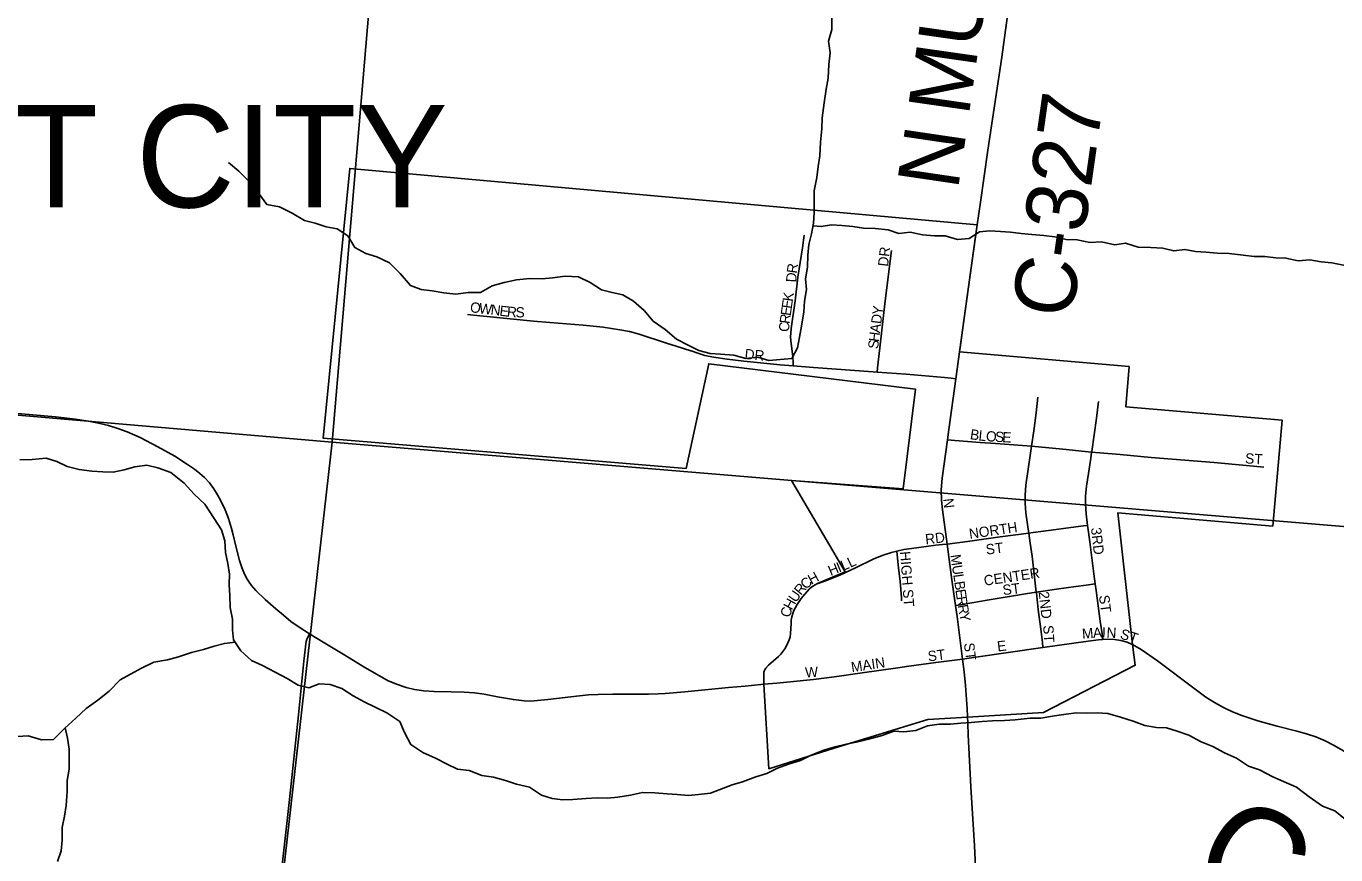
# Model space of a CAD drawing. Extents: x 1410790 to 1770854, y 566777 to 831614.
# Drawn here: x 1589830 to 1596228, y 734476 to 738525 of the extents above; entities that cross this region are included whole.
import ezdxf

# ---------------------------------------------------------------- set-up
doc = ezdxf.new("R2010")
doc.units = 0
for name, color, linetype in [('GM_X_City_Street', 7, 'Continuous'), ('GM_X_City_Street_Text', 7, 'Continuous'), ('GM_X_Corporation', 7, 'Continuous'), ('GM_X_Corporation_Text', 7, 'Continuous'), ('GM_X_County_Road', 7, 'Continuous'), ('GM_X_County_Road_Text', 7, 'Continuous'), ('GM_X_Minor_River', 7, 'Continuous'), ('GM_X_Minor_River_Text', 7, 'Continuous'), ('GM_X_Section', 7, 'Continuous'), ('GM_X_Township_Road', 7, 'Continuous')]:
    doc.layers.add(name, color=color, linetype=linetype)

msp = doc.modelspace()

# ---------------------------------------------------------------- linework, layer by layer
at = {"layer": 'GM_X_City_Street'}
for points in [[(1593577.7, 736865.5), (1593576.8, 736880.9), (1593575, 736911.3), (1593566.4, 736974.7), (1593564.6, 737005.9), (1593567.2, 737047.6), (1593586.3, 737183), (1593600.2, 737298.5), (1593621.9, 737441.7), (1593630.6, 737504.2)], [(1593986.7, 736834.9), (1593989.1, 736855.8), (1594000.5, 736953.2), (1594027.1, 737182.2), (1594056.8, 737428.7)], [(1591985, 737116.1), (1592045.5, 737109.3), (1592098.5, 737104.9), (1592146, 737100), (1592210.6, 737092.9), (1592307.6, 737083.2), (1592388.7, 737076.9), (1592551.3, 737063.4), (1592648.7, 737053.5), (1592729.4, 737041.9), (1592777.4, 737032.4), (1592824.7, 737019.9), (1592958.5, 736976.8), (1593004.7, 736961.7), (1593077.7, 736938.3), (1593078.2, 736938.1)], [(1593078.2, 736938.1), (1593110.6, 736927), (1593145.4, 736916.5), (1593187, 736907.9), (1593255, 736897.6), (1593335.7, 736888.1), (1593513.7, 736870.5), (1593577.7, 736865.5)], [(1594372.2, 736802), (1594373.8, 736813.6), (1594390.2, 736933.9), (1594392.9, 736953.8)], [(1593577.7, 736865.5), (1593675.8, 736857.7), (1593967.7, 736836.4), (1593986.7, 736834.9)], [(1593986.7, 736834.9), (1594129.8, 736823.9), (1594203.3, 736817.6)], [(1594203.3, 736817.6), (1594203.5, 736817.6), (1594315.8, 736807.6), (1594349.4, 736804.3), (1594372.2, 736802)], [(1594330.9, 736504.3), (1594337.6, 736553.7), (1594372.2, 736802)], [(1594741.8, 736472.2), (1594752.2, 736547.8), (1594763.4, 736635.3), (1594773, 736712.6)], [(1595035.2, 736443.9), (1595035.7, 736446.8), (1595058.5, 736610.1), (1595069.1, 736690.5)], [(1594329, 735994.4), (1594307.1, 736161.4), (1594302, 736209.5), (1594300.5, 736259.8), (1594305.6, 736316.6), (1594330.9, 736504.3)], [(1594330.9, 736504.3), (1594367.5, 736501.3), (1594429.2, 736496.4), (1594490.8, 736491.2), (1594565.3, 736486.1), (1594741.8, 736472.2)], [(1594727.7, 736047.6), (1594723.4, 736078.7), (1594713.9, 736147.5), (1594709.6, 736192.6), (1594709.6, 736233.4), (1594713.9, 736282), (1594735.6, 736427.9), (1594741.8, 736472.2)], [(1594741.8, 736472.2), (1594894.8, 736457.5), (1595035.2, 736443.9)], [(1595015.6, 736085.9), (1595009.1, 736141.6), (1595004.8, 736190.6), (1595004.9, 736207), (1595005.6, 736229.1), (1595010.8, 736276.8), (1595019.5, 736338.5), (1595030.8, 736414.8), (1595035.2, 736443.9)], [(1595035.2, 736443.9), (1595075.7, 736440), (1595174.3, 736431.5)], [(1595174.3, 736431.5), (1595325.6, 736417.9), (1595633.1, 736392.2), (1595859.6, 736372.2), (1595875.8, 736371)], [(1594727.7, 736047.6), (1594749.5, 736050.5), (1594861.7, 736065.3), (1594909.5, 736072.3), (1594995.2, 736083.2), (1595015.6, 736085.9)], [(1595052.4, 735800), (1595045.8, 735848.7), (1595026.4, 736005.1), (1595016.9, 736075.4), (1595015.6, 736085.9)], [(1594329, 735994.4), (1594428.7, 736007.6), (1594589, 736029.1), (1594727.7, 736047.6)], [(1594764.7, 735758.7), (1594743.8, 735934.9), (1594734.2, 735998.9), (1594727.7, 736047.6)], [(1593698.9, 735802.4), (1593747.1, 735819), (1593805.4, 735842.1), (1593882.1, 735877.7), (1593968.4, 735920.2), (1594012.5, 735939), (1594058.1, 735954.1), (1594083.3, 735960)], [(1594083.3, 735960), (1594117.3, 735967.7), (1594180, 735976.9), (1594274.6, 735988.4), (1594306.2, 735991.9), (1594329, 735994.4)], [(1594107, 735716.4), (1594106.1, 735732.6), (1594100, 735813.7), (1594091.7, 735877.3), (1594083.3, 735960)], [(1594369.7, 735694.6), (1594351.9, 735819.8), (1594329, 735994.4)], [(1593434, 735309.5), (1593433.3, 735332.5), (1593432.8, 735359.8), (1593433.8, 735368.1), (1593435.1, 735373), (1593436.6, 735376.8), (1593440.6, 735383.5), (1593444.1, 735388.4), (1593457.1, 735403.2), (1593505.1, 735444.6), (1593516.3, 735456.5), (1593526.6, 735469.1), (1593535.9, 735482.6), (1593544.8, 735497.8), (1593551.4, 735511.2), (1593557.4, 735526.4), (1593561.8, 735542), (1593564.3, 735558.1), (1593566.4, 735607), (1593567.9, 735623.3), (1593570.6, 735639.4), (1593574.7, 735655.2), (1593580.4, 735670.6), (1593587.5, 735685.2), (1593596, 735699.2), (1593616.8, 735728.7), (1593633.3, 735749.5), (1593645.5, 735762.6), (1593655, 735773.9), (1593668.9, 735786), (1593683.7, 735795.5), (1593696.1, 735801.4), (1593698.9, 735802.4)], [(1594369.7, 735694.6), (1594396.4, 735698.3), (1594412.6, 735700.5), (1594525.2, 735720.4), (1594712.2, 735750.8), (1594764.7, 735758.7)], [(1594764.7, 735758.7), (1594798.4, 735764.9), (1594862.8, 735773.7), (1594958.7, 735787.2), (1595008.2, 735794.2), (1595052.4, 735800)], [(1594797, 735488.5), (1594794.3, 735513), (1594787.1, 735578), (1594774.1, 735675.5), (1594765, 735756.6), (1594764.7, 735758.7)], [(1595089.1, 735528.5), (1595085.8, 735555.9), (1595076.8, 735617.1), (1595056.9, 735767.4), (1595052.4, 735800)], [(1594404.8, 735432.9), (1594377.4, 735641.2), (1594369.7, 735694.6)], [(1594797, 735488.5), (1595017.9, 735520.2), (1595082.2, 735528.2), (1595089.1, 735528.5)], [(1595089.1, 735528.5), (1595114.3, 735529.6), (1595146.2, 735527.9), (1595177.8, 735522.8), (1595208.7, 735514.4), (1595233.4, 735504.5)], [(1594404.8, 735432.9), (1594469.7, 735441.5), (1594797, 735488.5)], [(1593434, 735309.5), (1593497.9, 735315.4), (1593676.2, 735333.6), (1593789.5, 735347.3), (1593902.3, 735364.3), (1594099, 735391.7), (1594131.1, 735395.6), (1594274.7, 735415.9), (1594404.8, 735432.9)], [(1594429.9, 735117.3), (1594428.4, 735153.1), (1594426.6, 735188.8), (1594418.5, 735302.8), (1594411.9, 735369.5), (1594404.8, 735432.9)]]:
    msp.add_lwpolyline(points, dxfattribs=at)
at = {"layer": 'GM_X_Corporation'}
msp.add_lwpolyline([(1593596, 735699.2), (1593616.8, 735728.7), (1593633.3, 735749.5), (1593645.5, 735762.6), (1593655, 735773.8), (1593668.9, 735786), (1593683.7, 735795.5), (1593696.1, 735801.4), (1593830.5, 735858.3), (1593568.6, 736305.5), (1594115, 736264.3), (1594173.9, 736751.6), (1593164.3, 736875.5), (1593054.4, 736364.2), (1591281, 736511.6), (1591410.1, 737829.7), (1594476.1, 737554.1), (1594390.1, 736933.9), (1595217.8, 736861.4), (1595202.9, 736665.8), (1595965.7, 736599.1), (1595920.4, 736081.3), (1595163.3, 736147.5), (1595234.2, 735504.1), (1595248, 735402.8), (1594800.6, 735171.2), (1594428.6, 735149.3), (1594234.6, 735137.4), (1593776.9, 734997.4), (1593458, 734896.9), (1593434, 735309.5), (1593433.3, 735332.5), (1593432.8, 735359.8), (1593433.8, 735368.1), (1593435.1, 735373), (1593436.6, 735376.8), (1593440.7, 735383.5), (1593444.1, 735388.4), (1593457.1, 735403.2), (1593505.1, 735444.6), (1593516.3, 735456.5), (1593526.6, 735469.1), (1593535.8, 735482.6), (1593544.8, 735497.8), (1593551.4, 735511.2), (1593557.5, 735526.4), (1593561.8, 735542), (1593564.3, 735558.1), (1593566.4, 735607), (1593567.9, 735623.3), (1593570.6, 735639.4), (1593574.7, 735655.2), (1593580.4, 735670.6), (1593587.5, 735685.2)], close=True, dxfattribs=at)
at = {"layer": 'GM_X_County_Road'}
for points in [[(1594392.9, 736953.8), (1594411.3, 737086.9), (1594436, 737273.5), (1594465.9, 737486.3), (1594476.1, 737554.1), (1594492.2, 737665.6), (1594528.6, 737918.5), (1594595.6, 738372.7), (1594633.6, 738649.4), (1594678.1, 738958.2), (1594700.6, 739123.8), (1594726.1, 739302.4), (1594751.6, 739481), (1594793.7, 739771.3), (1594878.3, 740373.1), (1594945.6, 740844.7), (1594995.8, 741202.3), (1595017.6, 741364.8), (1595039.5, 741517.2), (1595049.7, 741590), (1595055.5, 741631.8), (1595060.4, 741667.1), (1595064.5, 741696.3)], [(1589695, 736640.3), (1589973.4, 736615.5), (1590070.6, 736604.2), (1590134.4, 736594.2), (1590182.8, 736585.2), (1590231.6, 736573.4), (1590277.6, 736559.5), (1590323.6, 736543.4), (1590387, 736514.4), (1590473.4, 736469.7), (1590555.8, 736423.2), (1590613.1, 736387.2), (1590652.2, 736360.7), (1590678.6, 736339.9), (1590700.3, 736319.5), (1590724.6, 736293), (1590746.4, 736263.9), (1590765, 736235.3), (1590779.8, 736208.4), (1590801.9, 736162.4), (1590817.5, 736119.4), (1590833.2, 736070.8), (1590840.8, 736039.9), (1590852.3, 735990.5), (1590871.8, 735914.1), (1590883.1, 735880.3), (1590892.6, 735855.9), (1590900.9, 735837.3), (1590909.5, 735823), (1590919.8, 735807.7), (1590930.8, 735792.6), (1590952.1, 735767.9), (1590997.6, 735723.1), (1591049.7, 735678.4), (1591087.1, 735647.2), (1591122.2, 735616.4), (1591162.6, 735588.6), (1591213.7, 735556.7)], [(1591213.7, 735556.7), (1591288, 735510.5), (1591386.2, 735451.3), (1591484.3, 735391.9), (1591555.1, 735350.1), (1591598.8, 735327), (1591643.5, 735308.2), (1591686.9, 735293.4), (1591726.4, 735284.3), (1591773, 735277.4), (1591822.4, 735273.9), (1591905.2, 735273), (1591969.5, 735271.3), (1592019.4, 735267), (1592066.7, 735260.5), (1592131.8, 735248.8), (1592209.9, 735234.4), (1592262, 735228.4), (1592294.5, 735227.5), (1592328.1, 735229.8), (1592377.6, 735235.3), (1592532.8, 735253.1), (1592577.1, 735257.4), (1592624.8, 735259.6), (1592695.6, 735260.9), (1592771.9, 735261.3), (1592821.5, 735261.8), (1592869.7, 735261.8), (1592917.8, 735263.1), (1592950.8, 735264.4), (1593047.1, 735272.6), (1593129.2, 735280.8), (1593195.6, 735287.4), (1593261.5, 735293.4), (1593341.8, 735300.2), (1593373, 735302.9), (1593434, 735309.5)], [(1595233.4, 735504.5), (1595234.2, 735504.1), (1595277.3, 735480.1), (1595357.3, 735423.5), (1595540.2, 735285.1), (1595593.5, 735246.5), (1595635.2, 735220), (1595678.6, 735196.3), (1595723.3, 735175.2), (1595769.2, 735156.6), (1595847.3, 735131.3), (1595942.1, 735104.2), (1596037.7, 735080.9), (1596084.8, 735067.9), (1596130.9, 735051.9), (1596175.8, 735032.8), (1596219.5, 735010.9), (1596261.7, 734986.4), (1596315.9, 734950.1), (1596395, 734891.9), (1596459.1, 734841.2), (1596685.1, 734651.7), (1596755.3, 734594.4)], [(1594451.4, 730178.2), (1594477.6, 730270.8), (1594573.8, 730601.6), (1594607.3, 730724.8), (1594624.1, 730790.3), (1594635.8, 730855.2), (1594644.5, 730925.2), (1594648.9, 730994.4), (1594651.4, 731044.5), (1594649.5, 731142.7), (1594639.6, 731339), (1594619, 731735.6), (1594597, 732108.1), (1594581.1, 732387.1), (1594565.1, 732669.1), (1594538.1, 733155.9), (1594525, 733384.8), (1594512.9, 733629.8), (1594499.8, 733875.3), (1594471.8, 734348.2), (1594462.3, 734520.2), (1594445.5, 734808.1), (1594432.1, 735062.7), (1594429.9, 735117.3)]]:
    msp.add_lwpolyline(points, dxfattribs=at)
at = {"layer": 'GM_X_Minor_River'}
for points in [[(1590818, 737859.2), (1590869, 737815.8), (1590925.8, 737760.2), (1590966.6, 737707.1), (1591005.3, 737654), (1591067.2, 737642.4), (1591128.5, 737610.9), (1591189.8, 737575.3), (1591241.6, 737562), (1591295.2, 737544.6), (1591349.1, 737535.3), (1591400.4, 737499.9), (1591435, 737442.9), (1591488.4, 737413.5), (1591542.1, 737398.2), (1591605.5, 737368.5), (1591656.4, 737317.1), (1591707, 737257.7), (1591758.7, 737238.4), (1591812.6, 737231.1), (1591870.5, 737221.6), (1591928.4, 737216.2), (1591988.7, 737222.8), (1592048.9, 737223.3), (1592105.8, 737256), (1592164.3, 737272.6), (1592224.7, 737285.2), (1592291, 737291.6), (1592351.1, 737290.1), (1592401.3, 737294.9), (1592463.6, 737303.4), (1592527.7, 737299.8), (1592585.1, 737272.3), (1592640.3, 737236.9), (1592692.1, 737223.6), (1592744, 737212.3), (1592797.3, 737180.9), (1592848.3, 737135.5), (1592893.1, 737084.3), (1592952.2, 737042.7), (1593007.2, 736995.2), (1593064.6, 736965.8), (1593116, 736940.4), (1593171.8, 736925), (1593221.8, 736921.8), (1593287.8, 736918.2), (1593345.5, 736900.7), (1593403.8, 736907.3), (1593457.5, 736891.9), (1593570, 736901.2), (1593597.3, 736952.7), (1593608.6, 737004.6), (1593617.9, 737058.5), (1593629.6, 737128.4), (1593632.9, 737180.5), (1593642.4, 737238.4), (1593637.6, 737290.7), (1593647, 737346.6), (1593648.5, 737406.8), (1593653.8, 737458.8), (1593667.1, 737510.6), (1593676.3, 737562.5), (1593679.6, 737612.6), (1593678.8, 737662.8), (1593680.2, 737720.9), (1593691.8, 737784.8), (1593699.1, 737838.8), (1593706.4, 737890.7), (1593710.1, 737958.8), (1593717.7, 738022.8), (1593719, 738077), (1593728.8, 738150.9), (1593738.5, 738216.9), (1593747.8, 738270.8), (1593751.4, 738336.9), (1593756.9, 738395), (1593750.2, 738451.3), (1593765.7, 738509.1), (1593765.2, 738571.3)], [(1596274.4, 737356.2), (1596208.6, 737367.9), (1596156.6, 737373.2), (1596100.7, 737382.6), (1596044.5, 737377.9), (1595984.7, 737391.5), (1595934.6, 737392.7), (1595880.7, 737400), (1595828.6, 737399.3), (1595774.7, 737406.7), (1595706.7, 737414.4), (1595648.6, 737415.8), (1595594.7, 737421.1), (1595542.6, 737424.4), (1595490.8, 737433.7), (1595436.5, 737427), (1595382.7, 737440.4), (1595324.7, 737443.8), (1595262.6, 737445.3), (1595201, 737464.9), (1595148.6, 737456.2), (1595082.9, 737471.8), (1595026.7, 737467.2), (1594964.9, 737480.8), (1594910.8, 737482.1), (1594855, 737495.5), (1594801.1, 737502.8), (1594743.1, 737506.3), (1594691.1, 737511.6), (1594639.2, 737518.8), (1594589.2, 737522.1), (1594537.1, 737525.4), (1594486.9, 737520.6), (1594436, 737487.7), (1594379.8, 737483.1), (1594320.1, 737500.6), (1594268, 737499.9), (1594208, 737505.4), (1594148.2, 737518.9), (1594093.9, 737512.2), (1594040.3, 737529.5), (1593978.3, 737537.1), (1593920.2, 737538.5), (1593868.3, 737545.8), (1593814.3, 737551.1), (1593764.3, 737554.4), (1593714, 737545.6), (1593674.1, 737549.9)], [(1592347.4, 734766.9), (1592288.2, 734806.4), (1592224.5, 734822), (1592170.8, 734839.4), (1592113.1, 734854.9), (1592055.2, 734864.3), (1591993.7, 734887.9), (1591937.7, 734895.2), (1591886.2, 734918.6), (1591828.8, 734948.1), (1591767.4, 734975.6), (1591708.2, 735015.2), (1591677.6, 735074.1), (1591654.8, 735126.8), (1591591.8, 735170.5), (1591538.3, 735195.9), (1591480.9, 735223.4), (1591427.5, 735252.7), (1591372.2, 735288.2), (1591314.6, 735307.7), (1591260.6, 735311), (1591210, 735292.2), (1591158.2, 735305.5), (1591104.9, 735336.9), (1591045.6, 735368.4), (1590984.2, 735402), (1590930.7, 735425.3), (1590877.8, 735472.8), (1590843, 735525.8), (1590838.2, 735576), (1590837.5, 735628.2), (1590826.9, 735684.6), (1590824.3, 735742.9), (1590821.6, 735797.1), (1590822.8, 735847.2), (1590814.1, 735899.6), (1590803.4, 735954), (1590800.8, 736010.2), (1590784.1, 736064.8), (1590747.3, 736119.8), (1590702.9, 736189.1), (1590650.1, 736238.6), (1590601.3, 736291.9), (1590536.4, 736343.6), (1590472.8, 736367.2), (1590419.1, 736380.6), (1590360.7, 736372), (1590308.3, 736357.2), (1590253.9, 736346.5), (1590203.8, 736347.8), (1590149.8, 736351.1), (1590087.9, 736358.6), (1590030.2, 736374.1), (1589978.6, 736397.4), (1589926.9, 736414.7), (1589858.6, 736408.3), (1589798.5, 736405.8)], [(1590849.9, 735515.3), (1590798.5, 735508.8), (1590748.1, 735496), (1590695.6, 735479.2), (1590637.1, 735464.6), (1590574.5, 735444.1), (1590520, 735429.4), (1590453.6, 735417), (1590392.8, 735388.4), (1590340, 735359.6), (1590289.1, 735330.7), (1590235.7, 735275.9), (1590180.5, 735231.1), (1590123.4, 735190.4), (1590072.1, 735143.5), (1590018.9, 735094.6), (1589963.4, 735039.8), (1589905.2, 735037.2), (1589839.6, 735056.9), (1589787.4, 735054.2)], [(1596276.2, 734648.4), (1596223.2, 734691.8), (1596163.6, 734713.3), (1596098.6, 734759), (1596035.6, 734806.7), (1595972.2, 734834.4), (1595920.6, 734857.7), (1595855.3, 734891.4), (1595801.6, 734908.8), (1595742.5, 734948.3), (1595685, 734973.8), (1595627.7, 735005.3), (1595570.1, 735028.8), (1595510.8, 735060.4), (1595453.1, 735079.8), (1595401.5, 735097.2), (1595351.4, 735098.4), (1595295.5, 735107.8), (1595237.9, 735129.3), (1595176.3, 735148.8), (1595114.6, 735166.4), (1595062.6, 735169.7), (1595010.5, 735168.9), (1594960.4, 735170.2), (1594910.1, 735163.4), (1594853.8, 735154.8), (1594787.4, 735144.3), (1594735.3, 735143.6), (1594660.9, 735135.4), (1594608.8, 735132.7), (1594550.6, 735130.1), (1594500.4, 735127.3), (1594446.2, 735122.6), (1594396, 735119.9), (1594345.8, 735115.1), (1594289.7, 735114.4), (1594233.4, 735105.8), (1594176.7, 735083.1), (1594118.4, 735076.5), (1594068.4, 735079.8), (1594011.8, 735059.1), (1593945.2, 735040.7), (1593892.8, 735027.9), (1593836.4, 735017.2), (1593782, 735004.5), (1593727.5, 734987.8), (1593664.8, 734963.3), (1593612, 734936.5), (1593553.5, 734919.9), (1593500.9, 734899.1), (1593448.2, 734874.3), (1593393.7, 734857.6), (1593328.9, 734833.1), (1593278.5, 734818.3), (1593173.3, 734776.8), (1593115, 734770.2), (1593064.8, 734765.4), (1593010.8, 734770.7), (1592960.8, 734773.9), (1592900.8, 734779.4), (1592840.7, 734780.9), (1592782.3, 734768.3), (1592719.9, 734757.8), (1592669.7, 734753), (1592619.6, 734754.2), (1592565.4, 734751.5), (1592501.2, 734747.1), (1592451, 734744.3), (1592399.1, 734751.6), (1592347.4, 734766.9)], [(1590020.9, 735096.5), (1590031.7, 735046.2), (1590040.4, 734991.8), (1590040, 734895.5), (1590030.6, 734839.6), (1590029.3, 734785.5), (1590025.6, 734717.4), (1590016.4, 734665.4), (1590005, 734609.6), (1590005.4, 734547.4), (1590000.2, 734495.3), (1589982.9, 734443.6)]]:
    msp.add_lwpolyline(points, dxfattribs=at)
at = {"layer": 'GM_X_Section'}
for points in [[(1586457.8, 742290.2), (1591780.2, 741853.1), (1591324.6, 736493), (1585962.5, 736952.7)], [(1591780.2, 741853.1), (1597046.2, 741516.8), (1596559.1, 736055.1), (1591324.6, 736493)], [(1585962.5, 736952.7), (1591324.6, 736493), (1590710.2, 731075.3), (1585323.6, 731643.3)], [(1591324.6, 736493), (1596559.1, 736055.1), (1596064.8, 730644), (1590710.2, 731075.3)]]:
    msp.add_lwpolyline(points, close=True, dxfattribs=at)
at = {"layer": 'GM_X_Township_Road'}
for points in [[(1591173.6, 735292.4), (1591186.9, 735421.6), (1591192.6, 735478.4), (1591195.4, 735507), (1591197.6, 735519.2), (1591200.3, 735528.3), (1591208.8, 735546.3), (1591213.7, 735556.7)], [(1591069.4, 734321.8), (1591087.3, 734485.1), (1591115.7, 734746.6), (1591160.1, 735160.4), (1591170, 735257.4), (1591173.6, 735292.4)]]:
    msp.add_lwpolyline(points, dxfattribs=at)

# ---------------------------------------------------------------- texts
at = {"layer": 'GM_X_City_Street_Text'}
for s, rotation, p in [('DR', 83.66379, (1594040.4, 737348.5)), ('R', 81.95919, (1593594.3, 737314.7)), ('D', 86.21645, (1593591.5, 737271.8)), ('O', 353.05392, (1591996.1, 737128)), ('W', 353.0554, (1592039.8, 737122.7)), ('N', 353.06133, (1592096.6, 737115.8)), ('E', 81.8583, (1593569.7, 737142.4)), ('K', 81.86264, (1593574.7, 737177.2)), ('E', 353.0444, (1592140.2, 737110.5)), ('R', 354.73285, (1592176.8, 737106.1)), ('S', 359.20472, (1592220.5, 737102.2)), ('R', 82.25451, (1593559.4, 737068.4)), ('E', 81.88535, (1593564.7, 737107.5)), ('D', 82.72294, (1594006.7, 737067.7)), ('Y', 82.72294, (1594012.3, 737111.3)), ('C', 85.40574, (1593556.3, 737029.6)), ('A', 82.72315, (1594001.1, 737024)), ('S', 83.84083, (1593991.9, 736945.7)), ('H', 82.79095, (1593995.6, 736980.4)), ('DR', 354.29265, (1593337.9, 736899.2)), ('B', 351.00086, (1594438.6, 736507.6)), ('L', 354.33985, (1594480.9, 736500.9)), ('O', 356.55894, (1594518, 736497.3)), ('S', 356.65876, (1594562, 736494.6)), ('E', 356.63835, (1594597.2, 736492.6)), ('ST', 356.41261, (1595783.9, 736388.9)), ('N', 276.55186, (1594310, 736215.2)), ('NORTH', 8.29705, (1594440, 736019.2)), ('RD', 6.33619, (1594224.7, 735992.8)), ('3RD', 276.58642, (1595031.5, 736072.6)), ('HIGH ST', 274.23162, (1594098.8, 735957.5)), ('ST', 7.12165, (1594521.2, 735942.7)), ('H', 22.4467, (1593760.2, 735838.2)), ('I', 22.47089, (1593800.9, 735855)), ('L', 22.45593, (1593821.3, 735863.4)), ('L', 25.02894, (1593856, 735877.9)), ('M', 278.15072, (1594345.1, 735940.8)), ('U', 278.13629, (1594352.5, 735888.5)), ('C', 41.75253, (1593638.6, 735770.1)), ('H', 28.27559, (1593665.6, 735794.7)), ('L', 278.1417, (1594358.8, 735845)), ('CENTER', 8.43298, (1594512.3, 735790.5)), ('U', 55.60066, (1593590.8, 735705.6)), ('R', 50.60805, (1593614.9, 735741)), ('B', 278.13698, (1594363.8, 735810.1)), ('E', 278.1417, (1594369.4, 735770.9)), ('ST', 7.11997, (1594603.2, 735744.6)), ('2ND', 276.33663, (1594776.3, 735760)), ('H', 61.1959, (1593570.2, 735668.2)), ('R', 278.53336, (1594374.4, 735735.7)), ('R', 280.28296, (1594380.5, 735694.9)), ('ST', 277.11998, (1595071.1, 735742.6)), ('C', 74.46158, (1593560.8, 735632.9)), ('Y', 280.77714, (1594387.7, 735655.5)), ('ST', 273.57465, (1594798.3, 735596.9)), ('M', 4.90583, (1594990.3, 735530.8)), ('A', 4.20087, (1595042.8, 735535.3)), ('I', 358.0326, (1595085.2, 735538.5)), ('N', 356.96079, (1595106.9, 735537.8)), ('ST', 341.55631, (1595170.3, 735534.8)), ('ST', 277.12166, (1594411.1, 735509.4)), ('E', 7.12165, (1594576.6, 735469.2)), ('MAIN', 8.47163, (1593863.6, 735368)), ('ST', 7.12165, (1594237.8, 735420.8)), ('W', 3.95386, (1593637.1, 735341.7))]:
    msp.add_text(s, height=50, rotation=rotation, dxfattribs=at).set_placement(p)
at = {"layer": 'GM_X_Corporation_Text'}
msp.add_text('TREMONT CITY', height=500, rotation=0.00001, dxfattribs=at).set_placement((1586875.1, 737639.3))
at = {"layer": 'GM_X_County_Road_Text'}
for s, rotation, p in [('MULBERRY', 81.86943, (1594434.4, 738081.2)), ('C-327', 81.87224, (1594939.9, 737090.4)), ('N', 81.59882, (1594381.6, 737720.2))]:
    msp.add_text(s, height=300, rotation=rotation, dxfattribs=at).set_placement(p)
at = {"layer": 'GM_X_Minor_River_Text'}
msp.add_text('Creek', height=500.01, rotation=330.00522, dxfattribs=at).set_placement((1595493.5, 734365.5))

doc.saveas('drawing.dxf')
